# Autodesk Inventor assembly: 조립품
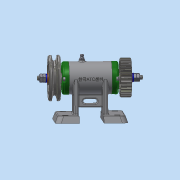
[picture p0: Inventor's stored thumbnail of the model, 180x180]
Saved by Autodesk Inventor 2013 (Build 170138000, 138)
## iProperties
Created: 2016-07
Part Number: 조립품
Document SubType Name: Assembly
Designer: Administrator
Author: Administrator
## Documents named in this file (16)
- C:\Users\Administrator\Desktop\460707V1015\조립품.iam
- C:\Users\Administrator\Desktop\460707V1015\V벨트풀리.ipt
- C:\Users\Administrator\Desktop\460707V1015\너트 M 8.ipt
- C:\Users\Administrator\Desktop\460707V1015\니플 M 6 x 0.75.ipt
- C:\Users\Administrator\Desktop\460707V1015\베어링 15 x 32 x 9.ipt
- C:\Users\Administrator\Desktop\460707V1015\본체.ipt
- C:\Users\Administrator\Desktop\460707V1015\볼트 M 6 x 8.ipt
- C:\Users\Administrator\Desktop\460707V1015\볼트 M4 x 12.ipt
- C:\Users\Administrator\Desktop\460707V1015\스퍼기어.ipt
- C:\Users\Administrator\Desktop\460707V1015\스프링와셔 8.ipt
- C:\Users\Administrator\Desktop\460707V1015\오일 실 15 25 7.ipt
- C:\Users\Administrator\Desktop\460707V1015\와셔 6x11.5.ipt
- C:\Users\Administrator\Desktop\460707V1015\와셔 8x17.ipt
- C:\Users\Administrator\Desktop\460707V1015\축.ipt
- C:\Users\Administrator\Desktop\460707V1015\커버.ipt
- C:\Users\Administrator\Desktop\460707V1015\키 3 x 3 x 12.ipt
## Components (11 placed, 3 different names)
1. V벨트풀리:1
2. KS B 2023 6002 - 15 x 32 x 9:1
3. KS B 2023 6002 - 15 x 32 x 9:3
4. ISO 4762 M4 x 12:1
5. ISO 4762 M4 x 12:3
6. ISO 4762 M4 x 12:4
7. ISO 4762 M4 x 12:5
8. ISO 4762 M4 x 12:2
9. ISO 4762 M4 x 12:6
10. ISO 4762 M4 x 12:7
11. ISO 4762 M4 x 12:8
